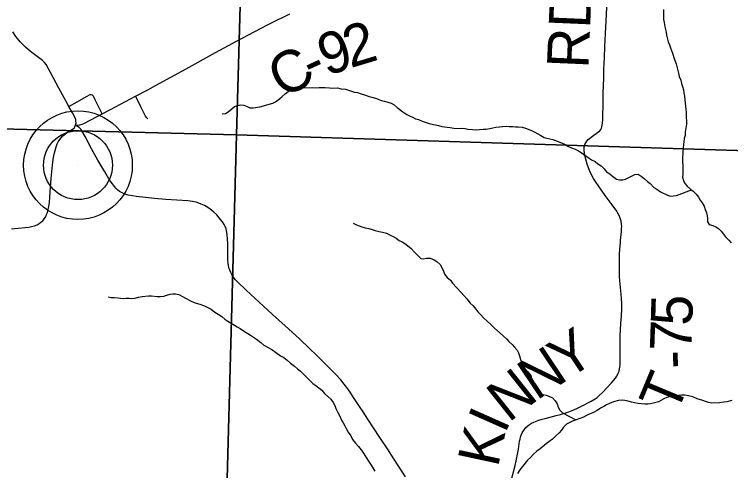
# Model space of a CAD drawing. Extents: x -3.3 to 34, y 0 to 56.8.
# Drawn here: x -1.696 to -0.715, y 29.247 to 29.871 of the extents above; entities that cross this region are included whole.
import ezdxf

# ---------------------------------------------------------------- set-up
doc = ezdxf.new("R2010")
doc.units = 0
for name, color, linetype in [('GM_X_Corporation', 7, 'Continuous'), ('GM_X_County_Road', 7, 'Continuous'), ('GM_X_State_Route', 7, 'Continuous'), ('GM_X_Township_Road', 7, 'Continuous'), ('GM_X_Township_Road_Text', 7, 'Continuous'), ('GM_X_Unincorporated', 7, 'Continuous'), ('GM_X_Unincorporated_Location', 7, 'Continuous'), ('GT_Project_Soil_Layers', 7, 'Continuous'), ('SH_Masking', 7, 'Continuous')]:
    doc.layers.add(name, color=color, linetype=linetype)

msp = doc.modelspace()

# ---------------------------------------------------------------- linework, layer by layer
at = {"layer": 'GM_X_Corporation'}
for points in [[(-2.39277, 30.73672), (-1.36367, 30.70347), (-1.39177, 29.70668), (-2.4143, 29.73246)], [(-0.36109, 30.66979), (-0.38619, 29.67495), (-1.39177, 29.70668), (-1.36367, 30.70347)], [(-1.39177, 29.70668), (-1.41929, 28.6974), (-2.4361, 28.72137), (-2.4143, 29.73246)], [(-1.39177, 29.70668), (-0.38619, 29.67495), (-0.41373, 28.6668), (-1.41929, 28.6974)]]:
    msp.add_lwpolyline(points, close=True, dxfattribs=at)
at = {"layer": 'GM_X_County_Road'}
msp.add_line((-1.52991, 29.75933), (-1.51333, 29.7683), dxfattribs=at)
for points in [[(-1.51333, 29.7683), (-1.50286, 29.77396), (-1.46076, 29.79683), (-1.42064, 29.81917), (-1.39093, 29.83528), (-1.36667, 29.84802), (-1.34939, 29.85709), (-1.33558, 29.86411), (-1.32802, 29.86761), (-1.31881, 29.872)], [(-1.61202, 29.71962), (-1.60607, 29.72022), (-1.60324, 29.72091), (-1.60059, 29.722), (-1.591, 29.72713), (-1.57573, 29.73509), (-1.56439, 29.7413), (-1.52991, 29.75933)]]:
    msp.add_lwpolyline(points, dxfattribs=at)
at = {"layer": 'GM_X_State_Route'}
for points in [[(-1.62765, 29.75715), (-1.63487, 29.77056), (-1.64631, 29.79201), (-1.6491, 29.79694), (-1.65247, 29.80269), (-1.65477, 29.80566), (-1.65748, 29.8082), (-1.663, 29.81256), (-1.67376, 29.82045), (-1.68083, 29.82645), (-1.68795, 29.83371), (-1.6916, 29.83824), (-1.69369, 29.84107), (-1.69785, 29.84759)], [(-1.61202, 29.71962), (-1.61148, 29.72305), (-1.61156, 29.72526), (-1.61194, 29.72764), (-1.61278, 29.72976), (-1.61635, 29.73657), (-1.62113, 29.74547), (-1.62481, 29.75206), (-1.62765, 29.75715)], [(-1.63735, 29.69405), (-1.63594, 29.69684), (-1.63471, 29.69886), (-1.63236, 29.70202), (-1.6296, 29.70511), (-1.62558, 29.70843), (-1.62315, 29.71018), (-1.61606, 29.71428), (-1.61423, 29.71573), (-1.61293, 29.71748), (-1.61202, 29.71962)], [(-1.69974, 29.57787), (-1.69571, 29.57845), (-1.6759, 29.58025), (-1.67253, 29.58083), (-1.66833, 29.58172), (-1.6648, 29.58321), (-1.66193, 29.58494), (-1.65946, 29.58675), (-1.65707, 29.5888), (-1.6551, 29.59135), (-1.65338, 29.59398), (-1.65182, 29.59719), (-1.65066, 29.60023), (-1.64943, 29.60426), (-1.64864, 29.6084), (-1.64787, 29.61388), (-1.64713, 29.62128), (-1.64624, 29.63492), (-1.64549, 29.64659), (-1.64475, 29.65596), (-1.64368, 29.66517), (-1.64269, 29.67322), (-1.64157, 29.67979), (-1.63884, 29.69006), (-1.63735, 29.69405)]]:
    msp.add_lwpolyline(points, dxfattribs=at)
at = {"layer": 'GM_X_Township_Road'}
for points in [[(-0.86619, 29.55845), (-0.86583, 29.56215), (-0.86501, 29.56987), (-0.86477, 29.57305), (-0.86444, 29.57794), (-0.86435, 29.58123), (-0.86454, 29.58405), (-0.86526, 29.58835), (-0.8664, 29.59236), (-0.86795, 29.59621), (-0.86954, 29.59938), (-0.87118, 29.60193), (-0.87738, 29.61059), (-0.88692, 29.62348), (-0.89445, 29.6341), (-0.90133, 29.64381), (-0.90309, 29.64685), (-0.90551, 29.65152), (-0.90825, 29.65753), (-0.91158, 29.66623), (-0.91369, 29.67305), (-0.91442, 29.67657), (-0.91524, 29.68126), (-0.91565, 29.68553), (-0.91582, 29.68791), (-0.91557, 29.69013), (-0.91483, 29.69326), (-0.91368, 29.69564), (-0.91211, 29.69802), (-0.91006, 29.70008), (-0.90249, 29.70583), (-0.89428, 29.71208), (-0.89296, 29.71364), (-0.89206, 29.71553), (-0.89148, 29.71751), (-0.89115, 29.71965), (-0.89074, 29.72293), (-0.89033, 29.72688), (-0.89017, 29.73206), (-0.88988, 29.74809), (-0.88959, 29.76395), (-0.88906, 29.78344), (-0.88872, 29.79599), (-0.88811, 29.81221), (-0.8874, 29.82693), (-0.88652, 29.84518), (-0.88571, 29.86187), (-0.88477, 29.88143)], [(-1.62113, 29.74547), (-1.60994, 29.75179), (-1.59617, 29.75957), (-1.59292, 29.76119), (-1.59158, 29.76155), (-1.59053, 29.76162), (-1.58938, 29.76124)], [(-1.57573, 29.73509), (-1.58035, 29.74449), (-1.58514, 29.75426), (-1.58764, 29.75929), (-1.58841, 29.76049), (-1.58938, 29.76124)], [(-1.51297, 29.72828), (-1.51443, 29.72979), (-1.5162, 29.73216), (-1.52263, 29.74475), (-1.52749, 29.75428), (-1.52991, 29.75933)], [(-1.56474, 29.64365), (-1.56652, 29.64626), (-1.57218, 29.65571), (-1.58155, 29.6719), (-1.59015, 29.68715), (-1.59917, 29.70425), (-1.6034, 29.71214), (-1.60508, 29.71428), (-1.60736, 29.71633), (-1.61202, 29.71962)], [(-1.16057, 29.23843), (-1.17043, 29.25384), (-1.17622, 29.2629), (-1.18517, 29.27648), (-1.1956, 29.29231), (-1.20428, 29.30547), (-1.2119, 29.31704), (-1.21851, 29.32707), (-1.22335, 29.33466), (-1.2251, 29.33735), (-1.23134, 29.347), (-1.23525, 29.35278), (-1.23942, 29.35853), (-1.24417, 29.36511), (-1.24901, 29.37103), (-1.25555, 29.37819), (-1.2663, 29.38903), (-1.27392, 29.39674), (-1.28216, 29.4048), (-1.29188, 29.41408), (-1.30572, 29.42729), (-1.3249, 29.44476), (-1.34242, 29.46053), (-1.35495, 29.47179), (-1.36659, 29.48271), (-1.37847, 29.49385), (-1.39039, 29.50503), (-1.39318, 29.50806), (-1.39486, 29.51014), (-1.39671, 29.51276), (-1.39834, 29.51535), (-1.39972, 29.51806), (-1.40109, 29.52137), (-1.40227, 29.52499), (-1.40293, 29.52754), (-1.40337, 29.53059), (-1.40373, 29.53552), (-1.40382, 29.55792), (-1.404, 29.56365), (-1.40454, 29.57001), (-1.40526, 29.57512), (-1.40607, 29.57799), (-1.40723, 29.58094), (-1.40875, 29.58381), (-1.41108, 29.58739), (-1.4135, 29.59059), (-1.41885, 29.59687), (-1.42283, 29.60062), (-1.42617, 29.60341), (-1.42966, 29.60602), (-1.43331, 29.60844), (-1.4357, 29.60978), (-1.43997, 29.61173), (-1.44349, 29.61304), (-1.44711, 29.61411), (-1.45202, 29.61519), (-1.45827, 29.61594), (-1.48865, 29.61795), (-1.50422, 29.61931), (-1.51645, 29.62054), (-1.52918, 29.62186), (-1.53434, 29.62274), (-1.54019, 29.62404), (-1.54422, 29.62512), (-1.54569, 29.62568), (-1.54917, 29.62737), (-1.55194, 29.62909), (-1.55413, 29.63073), (-1.55685, 29.63362), (-1.56474, 29.64365)], [(-1.01536, 29.23466), (-1.01043, 29.25397), (-1.00895, 29.25997), (-1.00805, 29.26457), (-1.00583, 29.27616), (-1.0041, 29.28718), (-1.0036, 29.28981), (-1.00303, 29.2926), (-1.00212, 29.29532), (-1.00057, 29.29836), (-0.99876, 29.30112), (-0.99549, 29.30559), (-0.99308, 29.30814), (-0.99078, 29.30978), (-0.98766, 29.31167), (-0.9847, 29.31307), (-0.97779, 29.31579), (-0.97327, 29.31719), (-0.96908, 29.31833), (-0.95409, 29.32208), (-0.94795, 29.32368), (-0.94227, 29.32549), (-0.93682, 29.32721), (-0.93001, 29.32978), (-0.92485, 29.33218), (-0.91923, 29.33498), (-0.90603, 29.34193), (-0.90085, 29.34489), (-0.89814, 29.34686), (-0.89567, 29.34899), (-0.89017, 29.35434), (-0.88476, 29.3601), (-0.87815, 29.36714), (-0.87293, 29.37328), (-0.87095, 29.3763), (-0.86909, 29.38012), (-0.86805, 29.38308), (-0.86729, 29.38612), (-0.86691, 29.38858), (-0.86666, 29.39182), (-0.86654, 29.41484), (-0.86642, 29.43233), (-0.86608, 29.439), (-0.86546, 29.4488), (-0.86485, 29.4584), (-0.86435, 29.46852), (-0.86427, 29.47214), (-0.86435, 29.47608), (-0.86468, 29.48184), (-0.86518, 29.48816), (-0.86682, 29.50674), (-0.86731, 29.51299), (-0.86748, 29.51702), (-0.86731, 29.54307), (-0.86698, 29.55014), (-0.86619, 29.55845)]]:
    msp.add_lwpolyline(points, dxfattribs=at)
at = {"layer": 'GM_X_Unincorporated'}
for radius in [0.0744, 0.04716]:
    msp.add_circle((-1.60883, 29.66488), radius, dxfattribs=at)
at = {"layer": 'GM_X_Unincorporated_Location'}
msp.add_line((-1.60883, 29.66488), (-1.60883, 29.66488), dxfattribs=at)
at = {"layer": 'GT_Project_Soil_Layers'}
for points in [[(-0.80722, 29.87794), (-0.80703, 29.86428), (-0.80622, 29.86012), (-0.80539, 29.85482), (-0.80457, 29.85066), (-0.80338, 29.84688), (-0.80296, 29.84309), (-0.80056, 29.83402), (-0.79898, 29.82949), (-0.79741, 29.82572), (-0.79622, 29.82194), (-0.79466, 29.81817), (-0.79188, 29.80948), (-0.78991, 29.80382), (-0.7867, 29.79096), (-0.78551, 29.78643), (-0.78354, 29.78114), (-0.78234, 29.7766), (-0.78114, 29.77245), (-0.77995, 29.76791), (-0.77913, 29.76337), (-0.77831, 29.75921), (-0.77743, 29.74974), (-0.77656, 29.74178), (-0.77612, 29.73685), (-0.77603, 29.7304), (-0.77559, 29.72586), (-0.77552, 29.72092), (-0.77659, 29.7156), (-0.77727, 29.71028), (-0.77759, 29.70572), (-0.77867, 29.70153), (-0.77937, 29.69697), (-0.7797, 29.69317), (-0.7804, 29.6886), (-0.7807, 29.68291), (-0.78133, 29.67341), (-0.78127, 29.66924), (-0.78084, 29.66507), (-0.78067, 29.65255), (-0.78099, 29.64837), (-0.77979, 29.64384), (-0.77784, 29.64007), (-0.77476, 29.63632), (-0.77016, 29.63221), (-0.76632, 29.62923), (-0.76248, 29.62511), (-0.75939, 29.62136), (-0.75706, 29.61722), (-0.75435, 29.61347), (-0.75126, 29.60896), (-0.75006, 29.60442), (-0.7481, 29.5999), (-0.74729, 29.59573), (-0.74686, 29.59195), (-0.7468, 29.58739), (-0.74447, 29.58363), (-0.73952, 29.58218), (-0.73571, 29.58072), (-0.73188, 29.57812), (-0.72842, 29.57438), (-0.72495, 29.57063), (-0.72225, 29.56688), (-0.71764, 29.56239), (-0.71455, 29.55864)], [(-1.41128, 29.73503), (-1.40674, 29.73585), (-1.40298, 29.73818), (-1.39811, 29.74205), (-1.39435, 29.74514), (-1.39058, 29.74671), (-1.38604, 29.74753), (-1.38149, 29.74722), (-1.37729, 29.74538), (-1.37348, 29.74353), (-1.36892, 29.74322), (-1.35984, 29.74486), (-1.35153, 29.74726), (-1.347, 29.74846), (-1.34209, 29.74967), (-1.33832, 29.75162), (-1.33307, 29.75587), (-1.32932, 29.75896), (-1.32519, 29.76243), (-1.31881, 29.76745), (-1.31468, 29.77017), (-1.3109, 29.77098), (-1.28777, 29.77131), (-1.28284, 29.771), (-1.27867, 29.77106), (-1.27032, 29.77117), (-1.26425, 29.77088), (-1.26008, 29.77056), (-1.25363, 29.77065), (-1.24831, 29.76959), (-1.24261, 29.76891), (-1.23004, 29.76492), (-1.22624, 29.76421), (-1.22091, 29.76239), (-1.21672, 29.76131), (-1.21025, 29.75913), (-1.20644, 29.75804), (-1.20149, 29.75659), (-1.19768, 29.75551), (-1.19387, 29.75367), (-1.1893, 29.75259), (-1.18435, 29.75114), (-1.17978, 29.74969), (-1.17596, 29.74747), (-1.17174, 29.74374), (-1.16407, 29.73777), (-1.15872, 29.73443), (-1.1549, 29.73259), (-1.15071, 29.73075), (-1.14651, 29.72853), (-1.1427, 29.72745), (-1.13774, 29.72525), (-1.13203, 29.72343), (-1.12784, 29.72197), (-1.12213, 29.72053), (-1.11528, 29.71911), (-1.11072, 29.71804), (-1.10312, 29.71701), (-1.09932, 29.71631), (-1.094, 29.71562), (-1.08944, 29.71531), (-1.08338, 29.71539), (-1.07882, 29.71508), (-1.07502, 29.71438), (-1.06857, 29.71371), (-1.06401, 29.71339), (-1.05909, 29.71384), (-1.05416, 29.71429), (-1.05037, 29.71435), (-1.04507, 29.71518), (-1.03675, 29.71682), (-1.03183, 29.71765), (-1.02766, 29.71771), (-1.02236, 29.71816), (-1.01856, 29.71784), (-1.01363, 29.71791), (-1.00984, 29.71758), (-1.00605, 29.71764), (-1.00073, 29.71695), (-0.99616, 29.7155), (-0.99235, 29.71404), (-0.98701, 29.71184), (-0.98319, 29.70999), (-0.97899, 29.70778), (-0.97517, 29.70556), (-0.97058, 29.70296), (-0.96677, 29.70188), (-0.96259, 29.7008), (-0.95879, 29.7001), (-0.95498, 29.69863), (-0.94659, 29.69572), (-0.94277, 29.6935), (-0.93742, 29.69054), (-0.93322, 29.6887), (-0.92789, 29.68688), (-0.92331, 29.68467), (-0.91871, 29.68132), (-0.9145, 29.67796), (-0.91068, 29.67574), (-0.9057, 29.6724), (-0.90074, 29.66981)], [(-0.90074, 29.66981), (-0.8969, 29.66683), (-0.89231, 29.66386), (-0.88847, 29.65974), (-0.885, 29.65562), (-0.88079, 29.65302), (-0.87695, 29.64966), (-0.87159, 29.64594), (-0.86741, 29.64486), (-0.86286, 29.64493), (-0.85908, 29.64574), (-0.85079, 29.65003), (-0.84627, 29.652), (-0.84173, 29.65282), (-0.83789, 29.64984), (-0.83368, 29.64648), (-0.82908, 29.64276), (-0.82524, 29.63977), (-0.82024, 29.63453), (-0.81642, 29.63231), (-0.81144, 29.62859), (-0.80152, 29.6238), (-0.79771, 29.62271), (-0.79392, 29.62277), (-0.78938, 29.62359), (-0.76885, 29.6312)], [(-1.2318, 29.58541), (-1.22759, 29.58319), (-1.22379, 29.58211), (-1.21998, 29.58064), (-1.21541, 29.57919), (-1.21046, 29.57812), (-1.2059, 29.57705), (-1.20171, 29.57559), (-1.19638, 29.57415), (-1.19181, 29.57307), (-1.18649, 29.57163), (-1.18152, 29.56905), (-1.17733, 29.56721), (-1.17312, 29.56499), (-1.16891, 29.56164), (-1.16509, 29.56017), (-1.16012, 29.55683), (-1.15246, 29.55087), (-1.1486, 29.54637), (-1.1436, 29.54113), (-1.13938, 29.53739), (-1.13558, 29.53669), (-1.13142, 29.53751), (-1.12649, 29.53758), (-1.12115, 29.53538), (-1.11733, 29.53315), (-1.1131, 29.52904), (-1.11077, 29.5249), (-1.10843, 29.52), (-1.10686, 29.51585), (-1.10338, 29.51134), (-1.09878, 29.50762), (-1.09607, 29.50348), (-1.08414, 29.49075), (-1.08068, 29.48662), (-1.07644, 29.48175), (-1.07181, 29.47613), (-1.06759, 29.47239), (-1.06412, 29.46789), (-1.06141, 29.46413), (-1.05718, 29.46002), (-1.05372, 29.45589), (-1.04873, 29.45141), (-1.04374, 29.44693), (-1.03913, 29.44244), (-1.02607, 29.43087), (-1.02223, 29.42713), (-1.01877, 29.42338), (-1.01417, 29.41965), (-1.01108, 29.4159), (-1.00762, 29.41178), (-1.00567, 29.40801), (-1.00409, 29.40386), (-1.00289, 29.39894), (-1.00131, 29.39441), (-0.99974, 29.39064), (-0.99742, 29.38688), (-0.9928, 29.38202), (-0.98894, 29.37676), (-0.98775, 29.37298), (-0.98504, 29.36847), (-0.98346, 29.36393), (-0.98189, 29.35978), (-0.97993, 29.35564), (-0.97647, 29.35189), (-0.97191, 29.35082), (-0.96772, 29.35012), (-0.96391, 29.34866), (-0.95933, 29.34645), (-0.95548, 29.34233), (-0.95277, 29.33819), (-0.9512, 29.33366), (-0.94887, 29.32952), (-0.9454, 29.32578), (-0.92727, 29.31621)], [(-1.56756, 29.48468), (-1.56338, 29.48397), (-1.5592, 29.48365), (-1.55427, 29.48334), (-1.55047, 29.48264), (-1.54667, 29.48231), (-1.54288, 29.48275), (-1.53871, 29.4828), (-1.53492, 29.48248), (-1.53075, 29.48291), (-1.52584, 29.48412), (-1.52092, 29.48495), (-1.51221, 29.48583), (-1.50804, 29.48589), (-1.50045, 29.48524), (-1.4959, 29.4853), (-1.49135, 29.48574), (-1.4872, 29.48694), (-1.48266, 29.48814), (-1.47888, 29.48857), (-1.47509, 29.48863), (-1.47052, 29.48793), (-1.46556, 29.48535), (-1.46135, 29.48275), (-1.45486, 29.47943), (-1.4499, 29.47684), (-1.44533, 29.47576), (-1.44076, 29.47431), (-1.43543, 29.47249), (-1.43084, 29.4699), (-1.42664, 29.46768), (-1.42128, 29.46358), (-1.41669, 29.46099), (-1.41172, 29.45764), (-1.4075, 29.45429), (-1.40367, 29.45131), (-1.39985, 29.44909), (-1.3945, 29.44612), (-1.39067, 29.44352), (-1.38685, 29.4413), (-1.38226, 29.43833), (-1.3727, 29.43239), (-1.36849, 29.42942), (-1.36428, 29.42682), (-1.35853, 29.42235), (-1.35431, 29.41861), (-1.34858, 29.41528), (-1.34324, 29.4127), (-1.33826, 29.40897), (-1.33136, 29.40376), (-1.32716, 29.40154), (-1.32256, 29.39819), (-1.31796, 29.39408), (-1.31221, 29.38961), (-1.30837, 29.38625), (-1.30454, 29.38327), (-1.29916, 29.37803), (-1.29493, 29.37392), (-1.29071, 29.3698), (-1.28724, 29.36606), (-1.28303, 29.36308), (-1.2792, 29.3601), (-1.27498, 29.35675), (-1.27113, 29.35225), (-1.2669, 29.34813), (-1.26268, 29.3444), (-1.25959, 29.33989), (-1.25726, 29.33575), (-1.25569, 29.33197), (-1.25335, 29.32745), (-1.25139, 29.32293), (-1.24788, 29.31577), (-1.24556, 29.31201), (-1.24324, 29.30825), (-1.24167, 29.30447), (-1.23895, 29.29958), (-1.23508, 29.29432), (-1.23274, 29.28942), (-1.22888, 29.28455), (-1.22465, 29.27967), (-1.22117, 29.27517), (-1.21808, 29.27066), (-1.21575, 29.2669), (-1.21188, 29.26088), (-1.2084, 29.25562), (-1.20529, 29.25035), (-1.20258, 29.24621)], [(-0.71354, 29.34275), (-0.72034, 29.34114), (-0.72451, 29.34032), (-0.73056, 29.33947), (-0.7408, 29.33933), (-0.74536, 29.34002), (-0.74955, 29.34148), (-0.75336, 29.34294), (-0.76098, 29.34511), (-0.76708, 29.34768), (-0.77279, 29.34912), (-0.77811, 29.35018), (-0.78266, 29.35011), (-0.79213, 29.34922), (-0.79743, 29.34838), (-0.80271, 29.34679), (-0.80686, 29.34483), (-0.81401, 29.34094), (-0.81968, 29.33934), (-0.82497, 29.33813), (-0.82876, 29.33769), (-0.83255, 29.33764), (-0.83749, 29.33832), (-0.84167, 29.33864), (-0.84699, 29.33971), (-0.85079, 29.34041), (-0.85536, 29.34186), (-0.85993, 29.34293), (-0.86372, 29.34326), (-0.86865, 29.34281), (-0.87545, 29.34082), (-0.88111, 29.33884), (-0.88525, 29.33688), (-0.88901, 29.33455), (-0.89353, 29.33221), (-0.89804, 29.32911), (-0.90407, 29.32599), (-0.90897, 29.32402), (-0.91274, 29.32207), (-0.91688, 29.32011), (-0.9316, 29.31459), (-0.93988, 29.3103), (-0.944, 29.30644), (-0.94698, 29.30223), (-0.94996, 29.29839), (-0.95483, 29.29377), (-0.95895, 29.28992), (-0.9642, 29.28604), (-0.96796, 29.28333), (-0.97621, 29.27639), (-0.98034, 29.27329), (-0.98559, 29.26866), (-0.98933, 29.26482), (-0.99345, 29.26096), (-1.00016, 29.25252), (-1.00389, 29.24791), (-1.00686, 29.24294)]]:
    msp.add_lwpolyline(points, dxfattribs=at)

# ---------------------------------------------------------------- texts
at = {"layer": 'GM_X_Township_Road_Text'}
for s, height, rotation, p in [('RD', 0.056818, 87.53133, (-0.9101, 29.79667)), ('5', 0.05682, 88.31272, (-0.76796, 29.44463)), ('Y', 0.05682, 33.73856, (-0.93955, 29.36982)), ('7', 0.05682, 88.0481, (-0.76916, 29.40937)), ('N', 0.05682, 33.78958, (-0.9811, 29.34202)), ('-', 0.05682, 91.76179, (-0.76844, 29.38702)), ('N', 0.05682, 38.48458, (-1.01924, 29.31163)), ('T', 0.05682, 67.30645, (-0.78953, 29.3224)), ('I', 0.05682, 66.12389, (-1.0243, 29.29597)), ('K', 0.05682, 77.85168, (-1.03387, 29.25001))]:
    msp.add_text(s, height=height, rotation=rotation, dxfattribs=at).set_placement(p)
at = {"layer": 'SH_Masking'}
for s, rotation, p in [('2', 16.83433, (-1.2359, 29.7976)), ('9', 18.84061, (-1.26852, 29.78646)), ('C', 28.59364, (-1.32835, 29.75539)), ('-', 24.72853, (-1.28828, 29.77727))]:
    msp.add_text(s, height=0.05682, rotation=rotation, dxfattribs=at).set_placement(p)

doc.saveas('drawing.dxf')
